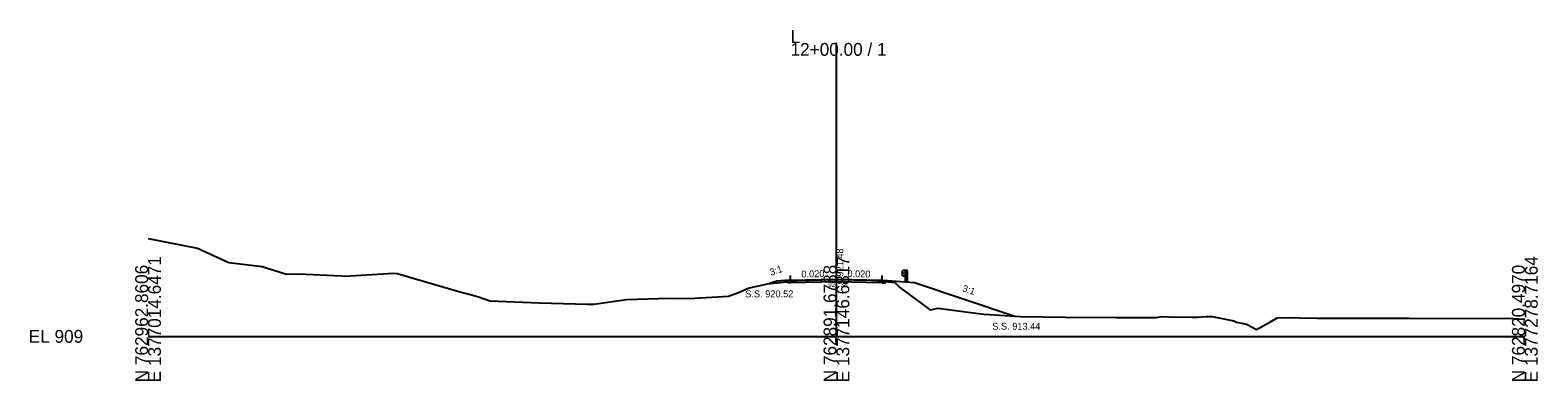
# Model space of a CAD drawing. Extents: x -26 to 303, y -10 to 6523.
# Drawn here: x -25.7 to 302.8, y 1990.3 to 2066.8 of the extents above; entities that cross this region are included whole.
import ezdxf

# ---------------------------------------------------------------- set-up
doc = ezdxf.new("R2010")
doc.units = 0
for name, color, linetype in [('Exist Cross Section Cell', 7, 'Continuous'), ('Exist XS Center Line Elevation Label', 7, 'Continuous'), ('Exist XS Ground Line', 7, 'Continuous'), ('Prop XS Dump Level', 7, 'Continuous'), ('Prop XS Elevation Labels', 7, 'Continuous'), ('Prop XS EOT Tick Mark', 7, 'Continuous'), ('Prop XS Finish Grade', 7, 'Continuous'), ('Prop XS Finish Grade Earthwork', 7, 'Continuous'), ('Prop XS Finish Grade Pavement', 7, 'Continuous'), ('Prop XS Guardrail', 7, 'Continuous'), ('Prop XS Pvmt Edge Slope', 7, 'Continuous'), ('Prop XS SE Text', 7, 'Continuous'), ('Prop XS Side Slope Text', 7, 'Continuous'), ('Prop XS SS Elevation Text', 7, 'Continuous'), ('Prop XS Subgrade Earthwork', 7, 'Continuous')]:
    doc.layers.add(name, color=color, linetype=linetype)

msp = doc.modelspace()

# ---------------------------------------------------------------- linework, layer by layer
at = {"layer": 'Exist Cross Section Cell'}
for p, q in [((150, 2000), (150, 2063.96)), ((0, 2000), (150, 2000)), ((150, 2000), (300, 2000))]:
    msp.add_line(p, q, dxfattribs=at)
at = {"layer": 'Exist XS Ground Line'}
for p, q in [((0, 2021.32), (10.8, 2019.25)), ((10.8, 2019.25), (17.61, 2016.14)), ((17.61, 2016.14), (24.83, 2015.23)), ((24.83, 2015.23), (30.16, 2013.58)), ((30.16, 2013.58), (32.83, 2013.65)), ((32.83, 2013.65), (42.17, 2013.18)), ((42.17, 2013.18), (42.92, 2013.15)), ((42.92, 2013.15), (53.46, 2013.75)), ((53.46, 2013.75), (54.31, 2013.71)), ((54.31, 2013.71), (67.74, 2009.79)), ((130.74, 2010.49), (134.97, 2011.47)), ((134.97, 2011.47), (139.84, 2011.98)), ((139.84, 2011.98), (140.65, 2012.16)), ((140.65, 2012.16), (141.47, 2012.18)), ((141.47, 2012.18), (149.45, 2012.39)), ((149.45, 2012.39), (150, 2012.38)), ((150, 2012.38), (157.47, 2012.28)), ((157.47, 2012.28), (158.33, 2012.26)), ((158.33, 2012.26), (159.5, 2012.13)), ((159.5, 2012.13), (162.72, 2011.72)), ((162.72, 2011.72), (163.79, 2010.64)), ((163.79, 2010.64), (170.21, 2005.94)), ((67.74, 2009.79), (70.8, 2008.99)), ((70.8, 2008.99), (72.22, 2008.54)), ((72.22, 2008.54), (74.47, 2007.77)), ((74.47, 2007.77), (85.27, 2007.28)), ((97.16, 2007), (104.27, 2008.01)), ((104.27, 2008.01), (113.54, 2008.36)), ((113.54, 2008.36), (118, 2008.24)), ((118, 2008.24), (126.5, 2008.8)), ((126.5, 2008.8), (128.99, 2009.69)), ((128.99, 2009.69), (130.74, 2010.49)), ((85.27, 2007.28), (95.72, 2007.01)), ((95.72, 2007.01), (97.16, 2007)), ((170.21, 2005.94), (170.54, 2005.76)), ((170.54, 2005.76), (170.85, 2005.88)), ((170.85, 2005.88), (172.12, 2006.12)), ((172.12, 2006.12), (174.38, 2005.85)), ((174.38, 2005.85), (178.74, 2005.28)), ((178.74, 2005.28), (182.09, 2004.88)), ((182.09, 2004.88), (190.09, 2004.36)), ((190.09, 2004.36), (199.84, 2004.17)), ((199.84, 2004.17), (210.85, 2004.15)), ((210.85, 2004.15), (216.67, 2004.15)), ((216.67, 2004.15), (219.73, 2004.13)), ((219.73, 2004.13), (220.91, 2004.31)), ((220.91, 2004.31), (222.49, 2004.25)), ((222.49, 2004.25), (227.44, 2004.19)), ((227.44, 2004.19), (227.77, 2004.17)), ((227.77, 2004.17), (228.69, 2004.2)), ((228.69, 2004.2), (230.5, 2004.36)), ((230.5, 2004.36), (231.88, 2004.36)), ((231.88, 2004.36), (236.59, 2003.38)), ((246.07, 2004.05), (249.09, 2004.12)), ((249.09, 2004.12), (250.89, 2004.05)), ((250.89, 2004.05), (254.66, 2004)), ((236.59, 2003.38), (237.15, 2003.13)), ((237.15, 2003.13), (239.37, 2002.63)), ((239.37, 2002.63), (241.55, 2001.49)), ((241.55, 2001.49), (244.45, 2003.07)), ((244.45, 2003.07), (246.07, 2004.05)), ((254.66, 2004), (271.41, 2003.98)), ((271.41, 2003.98), (274.43, 2003.98)), ((274.43, 2003.98), (274.87, 2003.96)), ((274.87, 2003.96), (277.98, 2003.93)), ((277.98, 2003.93), (296.14, 2003.94)), ((296.14, 2003.94), (300, 2003.79))]:
    msp.add_line(p, q, dxfattribs=at)
at = {"layer": 'Prop XS Dump Level'}
for p, q in [((140, 2012.28), (150, 2012.48)), ((150, 2012.48), (160, 2012.28))]:
    msp.add_line(p, q, dxfattribs=at)
at = {"layer": 'Prop XS EOT Tick Mark'}
for p, q in [((140, 2012.28), (140, 2013.28)), ((160, 2012.28), (160, 2013.28))]:
    msp.add_line(p, q, dxfattribs=at)
at = {"layer": 'Prop XS Finish Grade'}
for p, q in [((140, 2012.28), (138.9, 2012.19)), ((160, 2012.28), (161.1, 2012.19))]:
    msp.add_line(p, q, dxfattribs=at)
at = {"layer": 'Prop XS Finish Grade Earthwork'}
for p, q in [((137, 2012.04), (135.43, 2011.52)), ((138.9, 2012.19), (137, 2012.04)), ((161.1, 2012.19), (163, 2012.04)), ((163, 2012.04), (167, 2011.72)), ((167, 2011.72), (188.84, 2004.44))]:
    msp.add_line(p, q, dxfattribs=at)
at = {"layer": 'Prop XS Finish Grade Pavement'}
for p, q in [((140, 2012.28), (150, 2012.48)), ((150, 2012.48), (160, 2012.28))]:
    msp.add_line(p, q, dxfattribs=at)
at = {"layer": 'Prop XS Guardrail'}
for p, q in [((164.22, 2014.14), (164.19, 2014.08)), ((164.19, 2014.08), (164.22, 2014.02)), ((164.51, 2014.34), (164.22, 2014.14)), ((164.22, 2014.02), (164.51, 2013.82)), ((165.01, 2014.34), (164.51, 2014.34)), ((165.51, 2014.34), (165.01, 2014.34)), ((165.01, 2014.34), (165.01, 2011.84)), ((165.51, 2011.84), (165.51, 2014.34)), ((164.22, 2013.53), (164.19, 2013.47)), ((164.19, 2013.47), (164.22, 2013.41)), ((164.51, 2013.73), (164.22, 2013.53)), ((164.22, 2013.41), (164.51, 2013.21)), ((164.51, 2013.82), (164.51, 2013.73)), ((164.51, 2013.21), (165.01, 2013.21))]:
    msp.add_line(p, q, dxfattribs=at)
at = {"layer": 'Prop XS Pvmt Edge Slope'}
for p, q in [((140, 2012.28), (139.4, 2011.69)), ((160, 2012.28), (160.6, 2011.69))]:
    msp.add_line(p, q, dxfattribs=at)
at = {"layer": 'Prop XS Subgrade Earthwork'}
for p, q in [((139.4, 2011.69), (138.9, 2012.19)), ((140, 2011.7), (139.4, 2011.69)), ((150, 2011.9), (140, 2011.7)), ((160, 2011.7), (150, 2011.9)), ((160, 2011.7), (160.6, 2011.69)), ((160.6, 2011.69), (161.1, 2012.19))]:
    msp.add_line(p, q, dxfattribs=at)

# ---------------------------------------------------------------- texts
at = {"layer": 'Exist Cross Section Cell'}
for s, p in [('L', (140, 2063.96)), ('12+00.00 / 1', (140, 2061.16)), ('EL 909', (-26, 1998.6))]:
    msp.add_text(s, height=2.8, dxfattribs=at).set_placement(p)
for s, p in [('E 1377014.6471', (2.8, 1990)), ('E 1377146.6817', (152.8, 1990)), ('E 1377278.7164', (302.8, 1990)), ('N 762962.8606', (0, 1990)), ('N 762891.6788', (150, 1990)), ('N 762820.4970', (300, 1990))]:
    msp.add_text(s, height=2.8, rotation=90, dxfattribs=at).set_placement(p)
at = {"layer": 'Exist XS Center Line Elevation Label'}
msp.add_text('921.38', height=0.998, dxfattribs=at).set_placement((148.2, 2010.78))
at = {"layer": 'Prop XS Dump Level'}
for p in [(137, 2012), (163, 2012)]:
    msp.add_text('Case1', height=0.04, dxfattribs=at).set_placement(p)
at = {"layer": 'Prop XS Elevation Labels'}
msp.add_text(' 921.48', height=1.5, rotation=90, dxfattribs=at).set_placement((151.5, 2012.48))
at = {"layer": 'Prop XS SE Text'}
for rotation, p in [(1.1458, (142.38, 2012.83)), (358.8542, (152.38, 2012.93))]:
    msp.add_text('0.020', height=1.5, rotation=rotation, dxfattribs=at).set_placement(p)
at = {"layer": 'Prop XS Side Slope Text'}
for rotation, p in [(18.4349, (135.74, 2013.2)), (341.5651, (177.3, 2009.87))]:
    msp.add_text('3:1', height=1.5, rotation=rotation, dxfattribs=at).set_placement(p)
at = {"layer": 'Prop XS SS Elevation Text'}
for s, p in [('S.S. 920.52', (130.13, 2008.52)), ('S.S. 913.44', (183.96, 2001.45))]:
    msp.add_text(s, height=1.5, dxfattribs=at).set_placement(p)

doc.saveas('drawing.dxf')
